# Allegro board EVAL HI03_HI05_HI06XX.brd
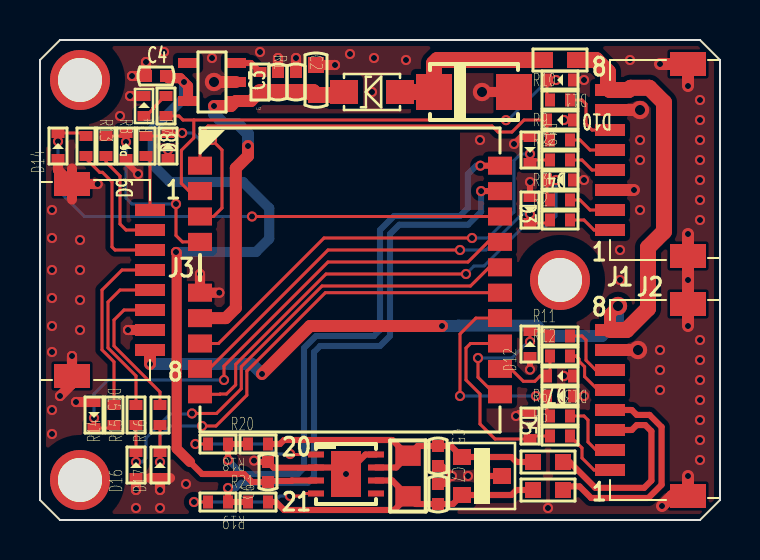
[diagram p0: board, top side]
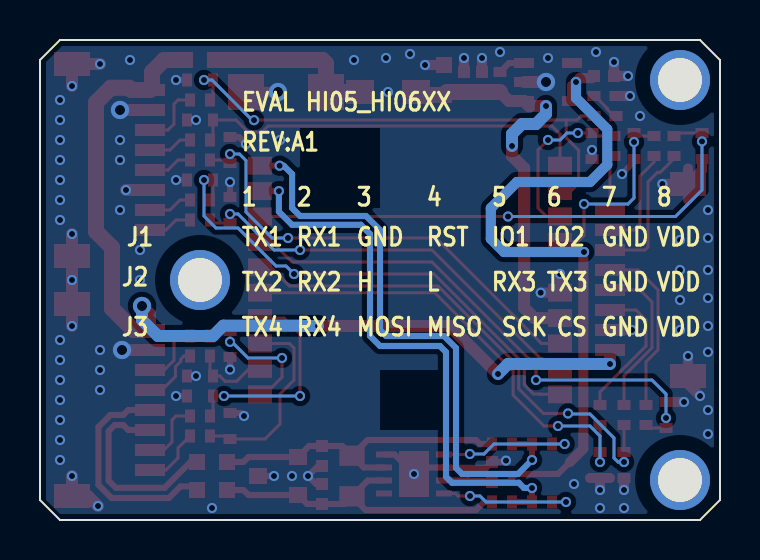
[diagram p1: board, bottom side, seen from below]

Outline 34 x 24 mm; copper layers: TOP, BOTTOM. Coordinates in mm from the lower left corner of the outline.
Outline path: 0,23 0,1 1,0 33,0 34,1 34,23 33,24 1,24 0,23

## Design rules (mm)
constraint set DEFAULT: min track width 0.152
net group CAN2: nets H L

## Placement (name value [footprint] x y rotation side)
C1  10uF  [C0603]  13.8 22 270 top
C2  0.1uF  [C0402]  12.8 21.9 270 top
C3  1uF  [C0402]  11.9 21.9 90 top
C4  1uF  [C0402]  5.8 22.2 0 top
C5  100pF  [C0402]  19.9 3.2 270 top
C6  0.1uF  [C0402]  11.4 2.4 90 top
C7  100pF  [C0402]  19.9 1.3 270 top
D1  RB160MM-60TR  [SOD123FL]  16.6 21.4 0 top
D2  SDD32A05L01  [DO-214AC]  21.7 21.4 0 top
D3  SBD52C05L01  [SOD-523]  24.5 15.5 270 top
D4  SBD52C05L01  [SOD-523]  26 17 180 top
D5  SBD52C05L01  [SOD-523]  24.5 4.7 270 top
D6  GREEN  [LED0402]  5.2 20.7 90 top
D7  SBD52C05L01  [SOD-523]  26 6.2 180 top
D8  SBD52C05L01  [SOD-523]  6.4 18.7 90 top
D9  SBD52C05L01  [SOD-523]  4.3 18.7 90 top
D10  SBD52C05L01  [SOD-523]  26 20 180 top
D11  SBD52C05L01  [SOD-523]  26 22 180 top
D12  SBD52C05L01  [SOD-523]  24.5 8.8 90 top
D13  SBD52C05L01  [SOD-523]  26 7.2 180 top
D14  SBD52C05L01  [SOD-523]  0.9 18.7 90 top
D15  SBD52C05L01  [SOD-523]  2.7 5.25 270 top
D16  SBD52C05L01  [SOD-523]  4.8 2.75 90 top
D17  SBD52C05L01  [SOD-523]  6 2.75 90 top
D18  SM24CANB-02HTG  [SOT23-3-0_95]  22.1 2.2 270 top
D19  SBD52C05L01  [SOD-523]  24.5 18.5 270 top
F1  100mA  [F0603]  25.4 2.9 180 top
F2  100mA  [F0603]  25.4 1.5 180 top
F3  300mA  [F0603]  26 23 180 top
H1  HOLE  [HOLE-2-MM]  2 22 0 top
H2  HOLE  [HOLE-2-MM]  2 2 0 top
H3  HOLE  [HOLE-2-MM]  26 12 0 top
J1  CON10  [5015680807_1]  28.5 18 270 top
J2  CON10  [5015680807_1]  28.5 6 270 top
J3  CON10  [5015680807_1]  5.5 12 90 top
R1  1K  [R0402]  11 21.9 270 top
R2  33R  [R0402]  26 15 0 top
R3  33R  [R0402]  26 16 0 top
R4  1K  [R0402]  6.3 20.7 90 top
R5  33R  [R0402]  26 4.2 0 top
R6  33R  [R0402]  26 5.2 0 top
R7  33R  [R0402]  5.3 18.7 270 top
R8  33R  [R0402]  3.3 18.7 270 top
R9  33R  [R0402]  26 19 0 top
R10  33R  [R0402]  26 21 0 top
R11  33R  [R0402]  26 9.2 0 top
R12  33R  [R0402]  26 8.2 0 top
R13  33R  [R0402]  2.3 18.7 270 top
R14  33R  [R0402]  3.7 5.25 90 top
R15  33R  [R0402]  4.8 5.25 90 top
R16  33R  [R0402]  6 5.25 90 top
R17  120R/DNP  [R0805]  18.4 2.2 90 top
R18  1K  [R0402]  8.9 3.8 180 top
R19  1K  [R0402]  8.9 0.9 180 top
R20  0R  [R0402]  10.9 3.8 0 top
R21  0R  [R0402]  10.9 0.9 0 top
R22  33R  [R0402]  26 18 0 top
U1  SPX3819M5-L-3-3/TR  [SOT23-5-0_95]  8.6 21.9 90 top
U2  HI05_HI06XX  [HI02_HI05_HI06]  15.5 12 0 top
U3  SIT3051TK  [HVSON8]  15.3 2.3 0 top

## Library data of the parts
C1-C7 = Capacity_Nonpolarity
D1 = diode
D2-D5 D7-D17 D19 = DIODE BI-DIR TRIG
D6 = LED
D18 = BAT54A/SOT
F1-F3 = Fuse
H1-H3 = HOLE
J1-J3 = CON10
R1-R22 = Res
U1 = XC6210
U2 = HI05_HI06XX
U3 = SIT3051TK

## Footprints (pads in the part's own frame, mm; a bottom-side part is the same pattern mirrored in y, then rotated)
5015680807_1
  rect 0.6x1.5 smd: 1(3.5,0) 2(2.5,0) 3(1.5,0) 4(0.5,0) 5(-0.5,0) 6(-1.5,0) 7(-2.5,0) 8(-3.5,0)
  rect 1.2x1.8 smd: 9(4.8,3.9) 10(-4.8,3.9)
C0402
  rect 0.6x0.6 smd: 1(-0.5,0) 2(0.5,0)
C0603
  rect 0.8x0.8 smd: 1(-0.75,0) 2(0.75,0)
DO-214AC
  rect 1.8x1.8 smd: 1(2,0) 2(-2,0)
F0603
  rect 0.8x0.8 smd: 1(-0.75,0) 2(0.75,0)
HI02_HI05_HI06
  rect 1.2x0.9 smd: 1(-7.5,5.715) 2(-7.5,4.445) 3(-7.5,3.175) 4(-7.5,1.905) 5(-7.5,-0.635) 6(-7.5,-1.905) 7(-7.5,-3.175) 8(-7.5,-4.445) 9(-7.5,-5.715) 10(7.5,-5.715) 11(7.5,-4.445) 12(7.5,-3.175) 13(7.5,-1.905) 14(7.5,-0.635) 15(7.5,0.635) 16(7.5,1.905) 17(7.5,3.175) 18(7.5,4.445) 19(7.5,5.715)
HOLE-2-MM
  round 3 hole 2.2: 1(0,0)
HVSON8
  rect 0.8x0.3 smd: 1(-1.5,0.975) 2(-1.5,0.325) 3(-1.5,-0.325) 4(-1.5,-0.975) 5(1.5,-0.975) 6(1.5,-0.325) 7(1.5,0.325) 8(1.5,0.975)
  rect 1.5x2.3 smd: 9(0,0)
LED0402
  rect 0.5x0.65 smd: 1(-0.5,0) 2(0.5,0)
R0402
  rect 0.5x0.65 smd: 1(-0.5,0) 2(0.5,0)
R0805
  rect 1.016x1.27 smd: 1(-1.016,0) 2(1.016,0)
SOD123FL
  rect 1.4x1.2 smd: 1(1.4,0) 2(-1.4,0)
SOD-523
  rect 0.5x0.65 smd: 1(-0.65,0) 2(0.65,0)
SOT23-3-0_95
  rect 0.8x0.9 smd: 1(-0.95,-1) 2(0.95,-1) 3(0,1)
SOT23-5-0_95
  rect 0.5x1 smd: 1(-0.95,-1.2) 2(0,-1.2) 3(0.95,-1.2) 4(0.95,1.2) 5(-0.95,1.2)

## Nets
GND: C1.1 C2.1 C3.2 C4.1 C5.2 C6.2 C7.1 D2.1 D3.1 D4.1 D5.1 D6.2(-) D7.1 D8.1 D9.1 D10.1 D11.1 D12.1 D13.1 D14.1 D15.1 D16.1 D17.1 D18.3 D19.1 J1.3 J1.7 J1.9 J1.10 J2.7 J2.9 J2.10 J3.7 J3.9 J3.10 U1.2(VSS) U2.5 U3.2 U3.8 U3.9
VCC: F3.1 J1.8 J2.8 J3.8
VDD: C1.2 C2.2 C3.1 D1.2 R1.2 U1.1 U2.6(VDD)
CAN_RX/L: R19.1 R21.1 U2.18
CAN_TX/H: R18.1 R20.1 U2.19
CS: D17.2 R16.1 U2.14
DP3V3: C4.2 C6.1 U1.5 U3.3(VCC)
H: F1.1 J2.3
IO1: D10.2 R9.1 U2.1
IO2: D11.2 R4.1 R10.1 U2.2
IO_1: J1.5 R9.2
IO_2: J1.6 R10.2
L: F2.1 J2.4
MISO: D15.2 R14.1 U2.16
MOSI: D14.2 R13.1 U2.17
NRST: J1.4 R22.2
RST: D19.2 R22.1 U2.7
RXD1: D4.2 R3.1 U2.9
RXD2: D7.2 R6.1 U2.13
RXD3: D13.2 R12.1 U2.11
RXD4: D9.2 R8.1 U2.4
SCK: D16.2 R15.1 U2.15
SPI_CS: J3.6 R16.2
SPI_MISO: J3.4 R14.2
SPI_MOSI: J3.3 R13.2
SPI_SCK: J3.5 R15.2
TXD1: D3.2 R2.1 U2.8
TXD2: D5.2 R5.1 U2.12
TXD3: D12.2 R11.1 U2.10
TXD4: D8.2 R7.1 U2.3
USART1_RX: J1.2 R3.2
USART1_TX: J1.1 R2.2
USART2_RX: J2.2 R6.2
USART2_TX: J2.1 R5.2
USART3_RX: J2.5 R12.2
USART3_TX: J2.6 R11.2
USART4_RX: J3.2 R8.2
USART4_TX: J3.1 R7.2
N2198535: D6.1 R4.2
N2224750: R1.1 U1.3
N2242059: C5.1 D18.1 F1.2 R17.2 R20.2 U3.7
N2242241: R18.2 U3.1
N2242331: C7.2 D18.2 F2.2 R17.1 R21.2 U3.6
N2242381: R19.2 U3.4
N2269635: D1.1(P) D2.2 F3.2

Pads without a net: H1 1; H2 1; H3 1; U1 4; U3 5

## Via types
v1: diameter 0.508, hole 0.305, TOP to BOTTOM, 126 vias
v2: diameter 0.914, hole 0.508, TOP to BOTTOM, 5 vias

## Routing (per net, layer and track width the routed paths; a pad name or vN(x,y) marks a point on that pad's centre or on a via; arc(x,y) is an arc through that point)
GND: length 50
  TOP w0.305: C5.2 20.1,2.7 v1(20.6,2.2) 20.2,1.8 C7.1 ; U3.8 16.27,3.28 v1(15.3,2.3) 14.97,2.62 U3.2 13.79,2.61 11.69,2.61 C6.2 10.8,2.9 10.73,2.97 v1(10.7,2.97) ; v1(23.8,5.2) 23.95,5.35 D5.1 ; D8.1 v1(6.4,18.5) ; D9.1 4.3,17.9 v1(4.9,17.3) ; D3.1 v1(24.5,16.9) ; D4.1 v1(27.2,17) ; v1(23.7,18.8) 24.05,19.15 D19.1 ; D18.3 v1(22.3,2.2) ; D13.1 v1(26.2,7.2) ; D11.1 v1(27.2,22) ; D7.1 v1(27.2,6.2) ; D12.1 v1(24.5,7.52) ; D10.1 v1(26.2,20)
  TOP w0.5: 1.6,17.58 J3.9 1.6,16.02 ; 5.5,2.1 D17.1 6.5,2.1
  TOP w0.508: D2.1 v2(22.1,21.4) ; v1(1,6.2) 1.6,6.8 J3.10 v1(1.6,8.2) ; D14.1 0.9,17.5 J3.9 v1(2.88,16.8) ; v1(4.6,22.2) C4.1 v1(5.3,22.9) ; D16.1 v1(4.8,1.5) ; v1(8,12.3) U2.5 v1(8.96,11.37) ; C1.1 v1(14.75,22.75) ; D17.1 v1(6,1.5) ; D15.1 v1(1.8,5.9) ; C2.1 v1(12.8,23.1) ; J3.7 v1(4.4,9.5) ; D6.2 v1(4.5,21.2) ; C3.2 v1(11.9,23.1)
  TOP w0.6: J1.7 v2(30,20.5) ; v1(32.4,2.2) J2.9 31.6,1.2 v1(31.1,0.7) ; v1(32.4,9.7) J2.10 v1(32.4,12) J1.9 v1(32.4,14.3) ; J2.7 v2(29.9,8.5) ; v1(31,22.8) J1.10 v1(32.4,21.7) ; J1.3 v1(29.7,16.5) ; U1.2 v2(8.7,21.9)
  vias: v1(0.6,15.5) v1(0.6,14.1) v1(0.6,12.5) v1(0.6,11.1) v1(0.6,9.7) v1(0.6,8.4) v1(0.6,5.5) v1(0.6,4.3) v1(2,14) v1(2,12.5) v1(2,11) v1(2,9.5) v1(4,20.2) v1(4.8,0.6) v1(6,0.6) v1(6.2,23.4) v1(7.3,1.8) v1(8.6,23.1) v1(11,23.4) v1(15.5,23.3) v1(16.6,21.4) v1(16.7,23.1) v1(18.3,23) v1(21.4,2.2) v1(22,19) v1(25.4,0.6) v1(29,13.5) v1(29,12) v1(29.5,23) v1(30,19) v1(30,18) v1(30,15.5) v1(31,8.5) v1(31,7.5) v1(31,6.5) v1(33,21) v1(33,20) v1(33,19) v1(33,18) v1(33,17) v1(33,16) v1(33,15) v1(33,9) v1(33,8) v1(33,7) v1(33,6) v1(33,5) v1(33,4) v1(33,3)
VCC: length 46.8
  TOP w0.6: v1(11.1,7.3) 13.5,9.7 v1(20.1,9.7) ; J2.8 28.5,10.3 v2(28.9,10.7) ; v1(5.5,7.8) J3.8
  TOP w0.8: J2.8 29.33,9.5 30.4,10.57 30.4,13.62 31.2,14.42 31.2,20.87 30.46,21.61 29.54,21.61 29.43,21.5 J1.8 28.4,21.6 28.4,22.4 27.8,23 F3.1
  BOTTOM w0.6: v1(11.1,7.3) 10.6,7.8 9.54,7.8 9.53,7.81 8.87,7.81 8.86,7.8 v1(5.5,7.8) ; v1(20.1,9.7) 20.9,9.7 20.92,9.72 24.83,9.72 25.35,9.2 28.1,9.2 28.9,10 v2(28.9,10.7)
VDD: length 20.4
  TOP w0.6: v1(10.4,18.7) 10.4,18.2 9.79,17.59 9.79,10.6 9.29,10.1 U2.6 ; R1.2 10.55,20.95 U1.1 9.55,20.7 v1(8.7,20.7)
  TOP w0.8: D1.2 15.05,21.25 C1.2 13.65,21.4 C2.2 C3.1 R1.2
  BOTTOM w0.6: v1(8.7,20.7) 8.7,20.3 9.2,19.8 9.9,19.8 10.4,19.3 v1(10.4,18.7)
CAN_RX/L: length 28.7
  TOP w0.305: U2.18 v1(22.05,16.45) ; v1(9.4,1.6) R19.1 R21.1
  BOTTOM w0.305: v1(22.05,16.45) 22.05,15.42 21.4,14.76 17.96,14.76 17.5,14.3 17.5,9.2 17,8.7 14,8.7 13.7,8.4 13.7,2.17 13.4,1.86 10.06,1.86 9.8,1.6 v1(9.4,1.6)
CAN_TX/H: length 29.5
  TOP w0.305: U2.19 v1(22.02,17.71) ; v1(9.4,3) R18.1 R20.1
  BOTTOM w0.305: v1(22.02,17.71) 21.82,17.71 21.39,17.29 21.39,15.6 21,15.2 17.7,15.2 17,14.5 17,9.5 16.7,9.2 13.8,9.2 13.2,8.6 13.2,2.6 12.9,2.3 10.1,2.3 v1(9.4,3)
CS: length 23.8
  TOP w0.152: v1(6,2.9) D17.2 R16.1 ; v1(8.1,4.7) 8.8,4.7 10.34,6.24 10.34,7.44 14.27,11.37 U2.14
  BOTTOM w0.152: v1(8.1,4.7) 6.5,4.7 6,4.2 v1(6,2.9)
DP3V3: length 37.6
  TOP w0.305: U3.3 12.59,1.97 12.57,1.95 11.45,1.95 C6.1 10.6,1.9 10.2,2.3 8.1,2.3 7.5,2.9
  TOP w0.508: v1(6.8,13.4) 6.83,13.37 6.83,3.57 7.5,2.9 ; C4.2 6.41,22.09 7.01,22.09 v1(7.2,21.9) 7.4,21.7 U1.5
  BOTTOM w0.508: v1(7.2,21.9) 7.2,21.1 5.64,19.54 5.64,17.76 6.5,16.9 10.15,16.9 11.46,15.59 11.46,14.06 10.8,13.4 v1(6.8,13.4)
H: length 9.9
  TOP w0.305: J2.3 29.59,4.5 29.83,4.75 30.27,4.75 30.57,4.44 30.57,1.97 30.21,1.61 27.77,1.61 26.48,2.9 F1.1
IO1: length 20.5
  TOP w0.152: R9.1 25.35,19.15 D10.2 24.2,20 23.6,19.4 22.9,19.4 22.6,19.7 8.4,19.7 8,19.3 U2.1
IO2: length 26.4
  TOP w0.152: v1(23.3,19.99) 23.19,19.99 23.18,20 7.69,20 ; R4.1 6.95,20.2 7.15,20 7.69,20 ; R10.1 25.35,21.15 D11.2 v1(25.8,22) ; U2.2 7.46,16.45 7.07,16.83 7.07,18.49 7.69,19.11 7.69,20
  BOTTOM w0.152: v1(25.8,22) 25.4,22 23.5,20.1 23.41,20.1 v1(23.3,19.99)
IO_1: length 2.2
  TOP w0.152: R9.2 27,19 27.5,18.5 J1.5
IO_2: length 3.2
  TOP w0.152: R10.2 27.1,21 27.3,20.8 27.3,19.8 27.6,19.5 J1.6
L: length 11.3
  TOP w0.305: J2.4 29.59,5.5 29.83,5.25 30.48,5.25 31.08,4.65 31.08,1.76 30.42,1.1 27.56,1.1 26.98,1.68 26.33,1.68 F2.1
MISO: length 26.6
  TOP w0.152: R14.1 3.55,4.6 D15.2 v1(2.7,5.1) ; U2.16 22.4,13.9 21.4,12.9 14.4,12.9 9.2,7.7 v1(9.2,7)
  BOTTOM w0.152: v1(2.7,5.1) 2.7,6.3 3.4,7 v1(9.2,7)
MOSI: length 27
  TOP w0.152: v1(0.9,18.93) D14.2 2.15,19.35 R13.1 ; U2.17 v1(10.6,15.18)
  BOTTOM w0.152: v1(10.6,15.18) 2.22,15.18 0.9,16.5 v1(0.9,18.93)
NRST: length 2.2
  TOP w0.152: R22.2 27.1,18 27.6,17.5 J1.4
RST: length 23.4
  TOP w0.152: v1(21.6,14.1) 14.2,14.1 8.93,8.82 U2.7 ; v1(24.5,18.3) D19.2 24.65,18 R22.1
  BOTTOM w0.152: v1(21.6,14.1) 22.4,14.1 23.7,15.4 23.7,17.97 24.03,18.3 v1(24.5,18.3)
RXD1: length 25.4
  TOP w0.152: R3.1 25.35,16.15 D4.2 v1(25.8,17) ; U2.9 8.99,6.29 9.01,6.3 9.33,6.3 9.78,6.76 9.78,7.78 14.3,12.3 v1(21.3,12.3)
  BOTTOM w0.152: v1(21.3,12.3) 21.7,12.7 22.2,12.7 24.1,14.6 25.2,14.6 25.8,15.2 v1(25.8,17)
RXD2: length 10.8
  TOP w0.152: R6.1 25.35,5.35 D7.2 v1(24.8,6.2) ; v1(21,6.2) 21,9.3 21.8,10.1 U2.13
  BOTTOM w0.152: v1(24.8,6.2) v1(21,6.2)
RXD3: length 3.8
  TOP w0.152: R12.1 25.5,7.35 D13.2 25.01,7.2 24.74,6.93 24.17,6.93 23.55,7.55 U2.11
RXD4: length 9.8
  TOP w0.152: U2.4 7.12,13.9 6.8,14.23 v1(6.8,15.8) ; R8.1 4.15,19.2 D9.2 v1(4.3,18.9)
  BOTTOM w0.152: v1(6.8,15.8) 4.6,15.8 4.3,16.1 v1(4.3,18.9)
SCK: length 25.3
  TOP w0.152: U2.15 22.46,12.63 21.53,11.7 14.1,11.7 10.06,7.66 10.06,6.56 8.83,5.33 v1(7.6,5.33) ; R15.1 D16.2 v1(4.8,2.9)
  BOTTOM w0.152: v1(7.6,5.33) 7.53,5.33 7.5,5.3 6.5,5.3 5.3,4.1 5.3,3.1 5.1,2.9 v1(4.8,2.9)
SPI_CS: length 7.2
  TOP w0.152: J3.6 4.2,10.5 3.7,10 3.7,8.7 6,6.4 R16.2
SPI_MISO: length 8.8
  TOP w0.152: R14.2 3.7,7.91 3.1,8.51 3.1,11.5 4.1,12.5 J3.4
SPI_MOSI: length 7.1
  TOP w0.152: J3.3 3.75,13.5 3.6,13.65 3.6,16.91 3.12,17.38 2.98,17.38 2.3,18.07 R13.2
SPI_SCK: length 8.1
  TOP w0.152: J3.5 4,11.5 3.4,10.9 3.4,8.6 4.8,7.2 R15.2
TXD1: length 21.2
  TOP w0.152: v1(21,13.5) 14.4,13.5 8.46,7.55 U2.8 ; R2.1 25.35,14.85 D3.2 v1(24.5,15.3)
  BOTTOM w0.152: v1(21,13.5) 22.3,13.5 24.1,15.3 v1(24.5,15.3)
TXD2: length 9.8
  TOP w0.152: U2.12 21.53,8.82 21.3,8.6 21.3,7 22,6.3 22,4.8 22.75,4.05 D5.2 24.65,4.2 R5.1
TXD3: length 7
  TOP w0.152: U2.10 22.75,6.29 21.9,7.14 v1(21.9,8.1) ; R11.1 25.25,9.45 D12.2 v1(24.5,8.91)
  BOTTOM w0.152: v1(24.5,8.91) 24.41,8.91 23.6,8.1 v1(21.9,8.1)
TXD4: length 8.4
  TOP w0.152: v1(8.6,19) 9.1,18.5 9.1,15.6 8.68,15.18 U2.3 ; v1(7.11,19.35) D8.2 6.25,19.2 R7.1
  BOTTOM w0.152: v1(8.6,19) 8,19 7.65,19.35 v1(7.11,19.35)
USART1_RX: length 2.2
  TOP w0.152: J1.2 27.5,15.5 27,16 R3.2
USART1_TX: length 2.2
  TOP w0.152: R2.2 27.2,15 27.7,14.5 J1.1
USART2_RX: length 3.3
  TOP w0.152: J2.2 27.8,3.5 27.4,3.9 27.4,5 27.2,5.2 R6.2
USART2_TX: length 3
  TOP w0.152: R5.2 27.1,3.6 27.1,3.1 27.7,2.5 J2.1
USART3_RX: length 3.1
  TOP w0.152: J2.5 27.9,6.5 27.23,7.17 27.23,7.66 26.95,7.94 26.95,8.05 26.8,8.2 R12.2
USART3_TX: length 3.3
  TOP w0.152: J2.6 27.79,7.5 27.3,7.99 27.3,9 27.1,9.2 R11.2
USART4_RX: length 5.3
  TOP w0.152: R8.2 3.3,17.9 4,17.2 4,14.8 4.3,14.5 J3.2
USART4_TX: length 2.8
  TOP w0.152: J3.1 5.5,18 R7.2
N2198535: length 1.5
  TOP w0.152: R4.2 6.26,21.2 5.64,20.59 5.64,20.54 5.3,20.2 D6.1
N2224750: length 1.4
  TOP w0.305: U1.3 10.55,22.85 R1.1
N2242059: length 16
  TOP w0.305: F1.2 23.82,2.9 23.57,3.15 D18.1 20.55,3.7 C5.1 18.88,3.7 R17.2 ; R20.2 12,3.8 12.2,4 17.62,4 R17.2 ; R17.2 17.81,2.62 U3.7
N2242241: length 6.9
  TOP w0.152: R18.2 v1(7.77,3.8) ; v1(12.51,3.3) 12.53,3.28 U3.1
  BOTTOM w0.152: v1(7.77,3.8) 11.3,3.8 11.8,3.3 v1(12.51,3.3)
N2242331: length 16.1
  TOP w0.305: R21.2 11.8,0.9 12.2,0.5 17.72,0.5 R17.1 ; R17.1 17.61,1.97 U3.6 ; R17.1 18.78,0.8 C7.2 20.65,0.8 D18.2 23.57,1.25 23.82,1.5 F2.2
N2242381: length 7
  TOP w0.152: 13.8,1.32 13.22,1.32 13.1,1.2 v1(12.5,1.2) ; R19.2 v1(7.7,0.9)
  BOTTOM w0.152: v1(12.5,1.2) 12,1.2 11.7,0.9 v1(7.7,0.9)
N2269635: length 8.7
  TOP w0.8: F3.2 19.87,23 19.7,22.83 D2.2 D1.1

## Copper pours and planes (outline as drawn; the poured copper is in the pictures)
GND on TOP: 1.3,23.7 32.9,23.7 33.7,22.9 33.7,1 33,0.3 1.3,0.3 0.3,1.3 0.3,22.7 ; 13 cut-outs
GND on BOTTOM: 1.3,23.7 32.9,23.7 33.7,22.9 33.7,1 33,0.3 1.3,0.3 0.3,1.3 0.3,22.7 ; 1 cut-out

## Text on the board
Ref Des/Silkscreen Bottom: 8 | VDD | 7 | GND | CS | 6 | IO2 | TX3 | SCK | 5 | IO1 | RX3 | 4 | RST | L | MISO | 3 | H | MOSI | 2 | RX1 | RX2 | RX4 | EVAL HI05_HI06XX | REV:A1 | 1 | TX1 | TX2 | TX4 | J1 | J2 | J3
Ref Des/Silkscreen Top: 1 | J3 | 8 | 20 | 21 | J1 | J2
User.8: FIGURE | FINISHED_SIZE | 10.0 | 12.0 | 20.0 | 86.614 | DRILL CHART: TOP to BOTTOM | ALL UNITS ARE IN MILS | PLATED | QTY | 126 | 2 | 3
